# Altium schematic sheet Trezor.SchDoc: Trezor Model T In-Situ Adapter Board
size B; Engineer: Joe Grand; Revision: A; SheetNumber: 1; SheetTotal: 1; PageSetup: Record=PageOptions¦CenterHorizontal=True¦CenterVertical=True¦PrintScale=0.70¦XCorrection=1.00¦YCorrection=1.00¦PrintKind=0¦BorderSize=5000000¦LeftOffset=0¦BottomOffset=0¦Orientation=2¦PaperLength=1000¦PaperWidth=1000¦Scale=100¦PaperSource=7¦PrintQuality=-4¦MediaType=1¦DitherType=10¦PrintScaleMode=1¦PaperKind=Letter
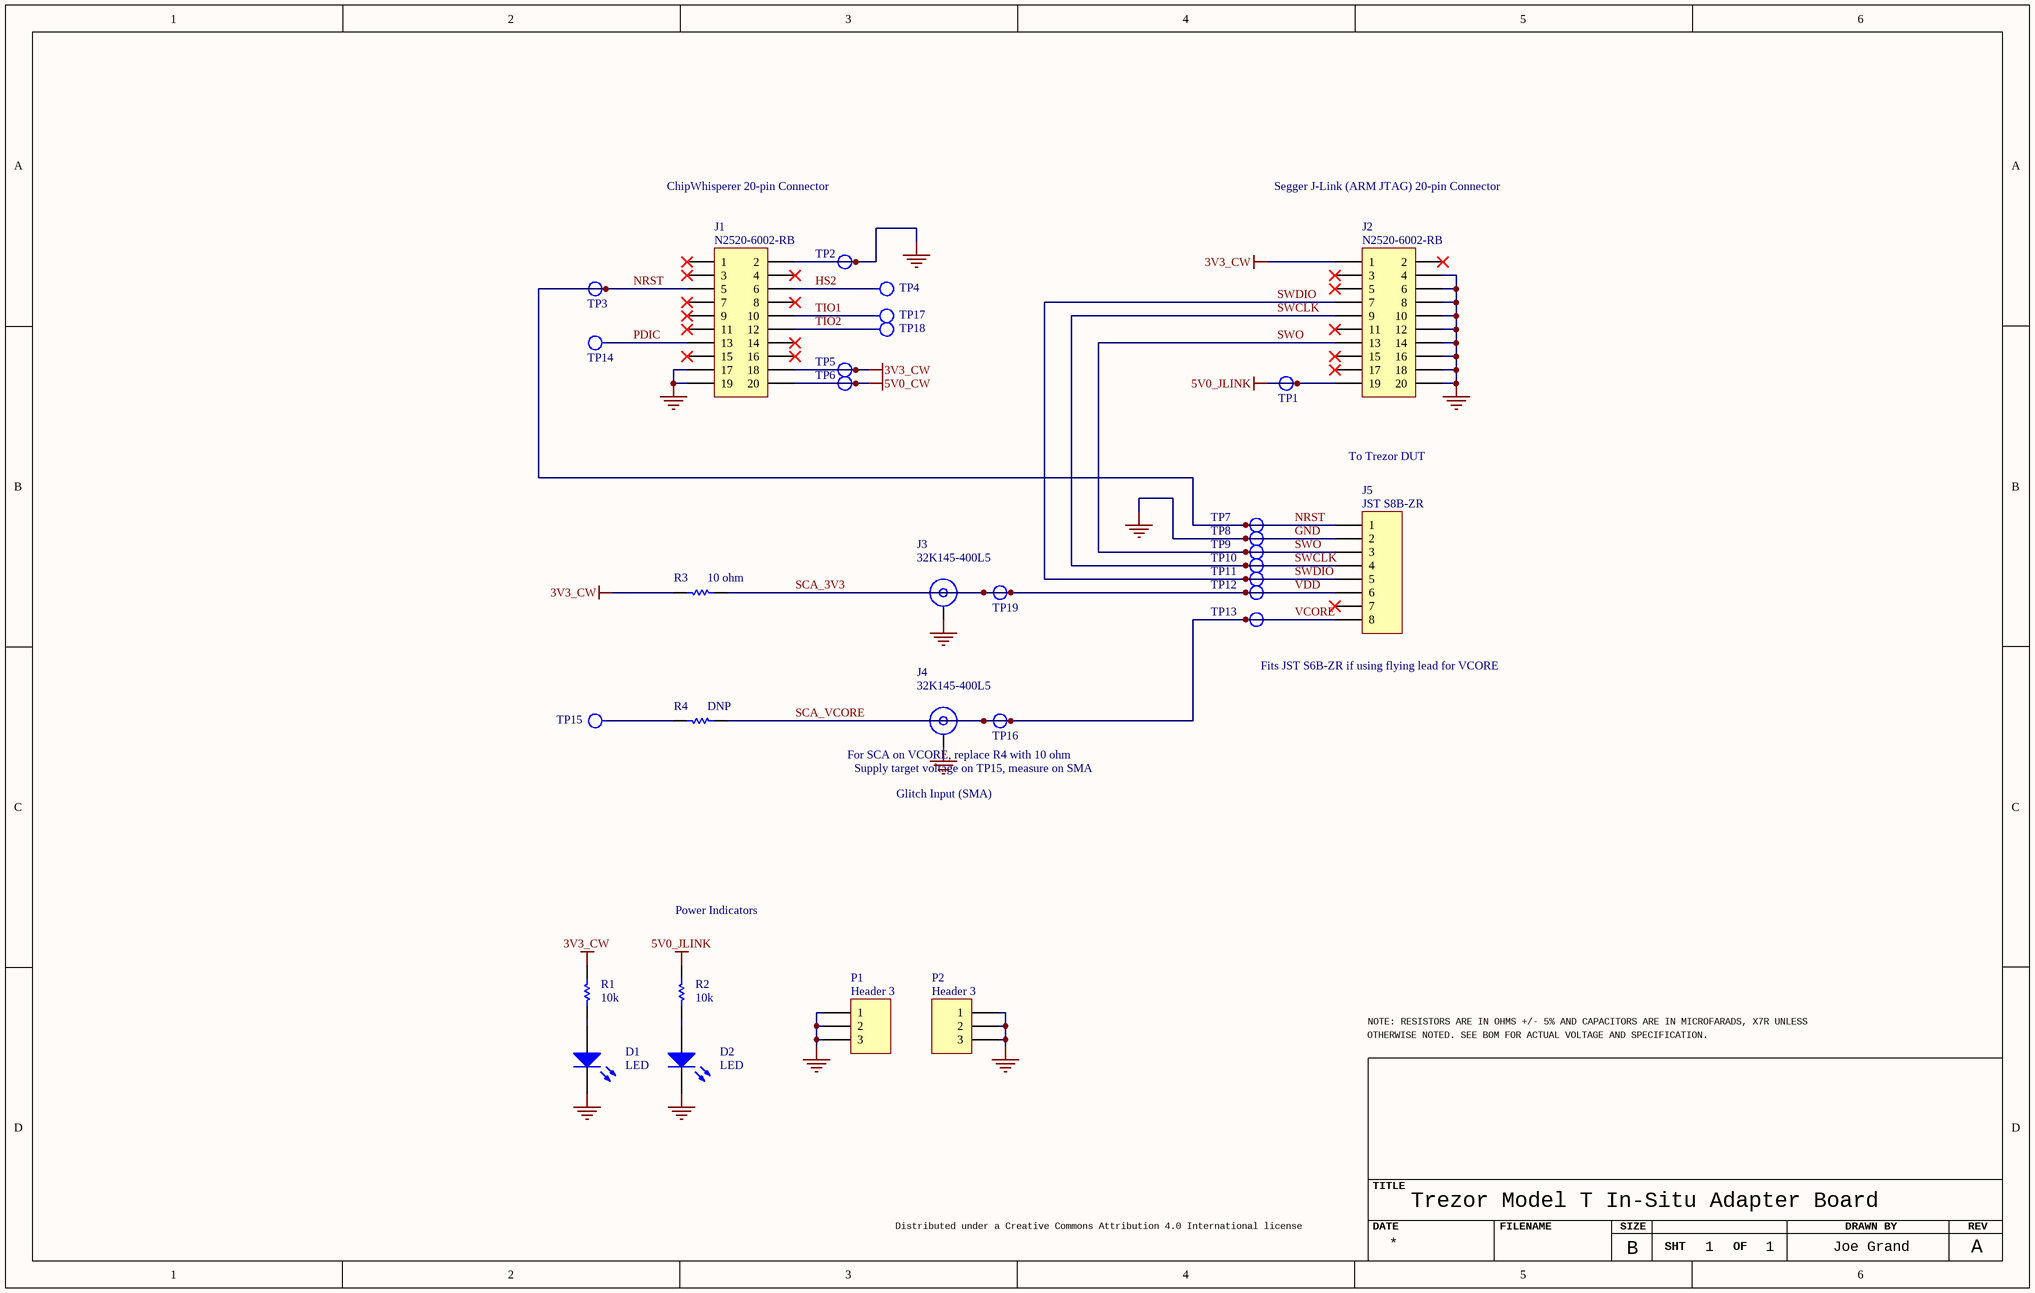
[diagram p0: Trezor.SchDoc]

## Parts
*  Page Size: B  RevCode: A  Page Count: 1  OrgName: Joe Grand  Title: Trezor Model T In-Situ Adapter Board  (hidden comment: GIS Title Block)  (graphical)
D1  LED  [CC2012-0805 LED]
D2  LED  [CC2012-0805 LED]
J1  N2520-6002-RB  [HDR2X10 - SHROUD]
J2  N2520-6002-RB  [HDR2X10 - SHROUD]
J3  32K145-400L5  [ROS-32K145-400L5_V]
J4  32K145-400L5  [ROS-32K145-400L5_V]
J5  JST S8B-ZR  [JST-S8B-ZR]
P1  Header 3  [HEADER3]
P2  Header 3  [HEADER3]
R1  value 10k  [CC2012-0805]  (hidden comment: Res1)
R2  value 10k  [CC2012-0805]  (hidden comment: Res1)
R3  value 10 ohm  [CC2012-0805]  (hidden comment: Res1)
R4  value DNP  [CC2012-0805]  (hidden comment: Res1)
TP1  TESTPOINT  [TESTPOINT - DOUBLE]  (value not drawn)
TP2  TESTPOINT  [TESTPOINT - DOUBLE]  (value not drawn)
TP3  TESTPOINT  [TESTPOINT - DOUBLE]  (value not drawn)
TP4  TESTPOINT  [TESTPOINT - DOUBLE]  (value not drawn)
TP5  TESTPOINT  [TESTPOINT - DOUBLE]  (value not drawn)
TP6  TESTPOINT  [TESTPOINT - DOUBLE]  (value not drawn)
TP7  TESTPOINT  [TESTPOINT - DOUBLE]  (value not drawn)
TP8  TESTPOINT  [TESTPOINT - DOUBLE]  (value not drawn)
TP9  TESTPOINT  [TESTPOINT - DOUBLE]  (value not drawn)
TP10  TESTPOINT  [TESTPOINT - DOUBLE]  (value not drawn)
TP11  TESTPOINT  [TESTPOINT - DOUBLE]  (value not drawn)
TP12  TESTPOINT  [TESTPOINT - DOUBLE]  (value not drawn)
TP13  TESTPOINT  [TESTPOINT - DOUBLE]  (value not drawn)
TP14  TESTPOINT  [TESTPOINT - DOUBLE]  (value not drawn)
TP15  TESTPOINT  [TESTPOINT - DOUBLE]  (value not drawn)
TP16  TESTPOINT  [TESTPOINT - DOUBLE]  (value not drawn)
TP17  TESTPOINT  [TESTPOINT - DOUBLE]  (value not drawn)
TP18  TESTPOINT  [TESTPOINT - DOUBLE]  (value not drawn)
TP19  TESTPOINT  [TESTPOINT - DOUBLE]  (value not drawn)

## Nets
3V3_CW: J1.18 J2.1 R1.1 R3.1 TP5.1
5V0_CW: J1.20 TP6.1
5V0_JLINK: J2.19 R2.1 TP1.1
GND: D1.2(K) D2.2(K) J1.2 J1.17 J1.19 J2.4 J2.6 J2.8 J2.10 J2.12 J2.14 J2.16 J2.18 J2.20 J3.MP J4.MP J5.2 P1.1 P1.2 P1.3 P2.1 P2.2 P2.3 TP2.1 TP8.1
HS2: J1.6 TP4.1
NRST: J1.5 J5.1 TP3.1 TP7.1
PDIC: J1.13 TP14.1
SCA_3V3: J3.1 J5.6 R3.2 TP12.1 TP19.1  [also labelled VDD]
SCA_VCORE: J4.1 J5.8 R4.2 TP13.1 TP16.1  [also labelled VCORE]
SWCLK: J2.9 J5.4 TP10.1
SWDIO: J2.7 J5.5 TP11.1
SWO: J2.13 J5.3 TP9.1
TIO1: J1.10 TP17.1
TIO2: J1.12 TP18.1
NetD1_1: D1.1(A) R1.2
NetD2_1: D2.1(A) R2.2
NetR4_1: R4.1 TP15.1

Not connected (* = marked no-connect by the designer): J1 1* 3* 4* 7* 8* 9* 11* 14* 15* 16*; J2 2* 3* 5* 11* 15* 17*; J5 7*

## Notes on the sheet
- ChipWhisperer 20-pin Connector
- Segger J-Link (ARM JTAG) 20-pin Connector
- To Trezor DUT
- Fits JST S6B-ZR if using flying lead for VCORE
- For SCA on VCORE, replace R4 with 10 ohm
- Supply target voltage on TP15, measure on SMA
- Glitch Input (SMA)
- Power Indicators
- (near *) OTHERWISE NOTED. SEE BOM FOR ACTUAL VOLTAGE AND SPECIFICATION.
- (near *) NOTE: RESISTORS ARE IN OHMS +/- 5% AND CAPACITORS ARE IN MICROFARADS, X7R UNLESS
- Distributed under a Creative Commons Attribution 4.0 International license

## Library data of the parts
D1 D2 = LED0: Typical LED
J1 J2 = Header 10X2: Header, 10-Pin, Dual row
J3 J4 = 32K145-400L5: SMA Right Angle Jack, Edge Mount, Up to 18 GHz, -55 to 155 degC; Design Note 1: Footprint in library is a generic example - only application specific footprint delivers High Performance; Desgin Note 2: For more information about DRC setting, please look at following webpage, http://techdocs.altium.com/display/SCRT/Design+Rule+for+Edge-Mount+Connectors
J5 = Header 8: Header, 8-Pin
P1 P2 = Header 3: Header, 3-Pin
R1-R4 = Res1: Resistor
